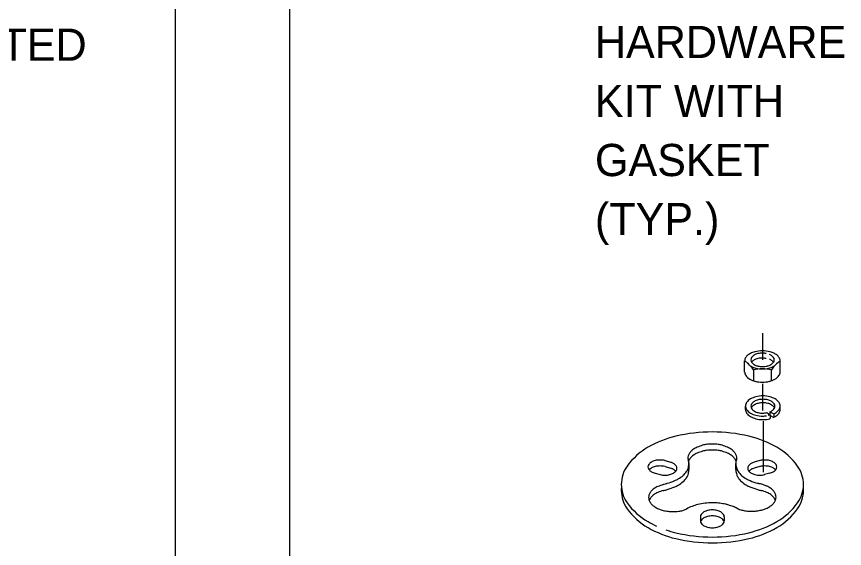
# Model space of a CAD drawing. Extents: x -224.9 to -217.6, y 224 to 234.
# Drawn here: x -219.614 to -218.072, y 230.281 to 231.272 of the extents above; entities that cross this region are included whole.
import ezdxf

# ---------------------------------------------------------------- set-up
doc = ezdxf.new("R2010")
doc.units = 0
for name, color, linetype in [('DETL-DIMS', 7, 'Continuous'), ('DETL-LINE', 7, 'Continuous'), ('DETL-NOTE', 7, 'Continuous')]:
    doc.layers.add(name, color=color, linetype=linetype)

msp = doc.modelspace()

# ---------------------------------------------------------------- linework, layer by layer
at = {"layer": 'DETL-DIMS'}
for p, q in [((-218.2241, 230.6326), (-218.2241, 230.6825)), ((-218.2241, 230.538), (-218.2241, 230.5881)), ((-218.2234, 230.4235), (-218.2234, 230.5184))]:
    msp.add_line(p, q, dxfattribs=at)
at = {"layer": 'DETL-LINE'}
for p, q in [((-219.3182, 231.7582), (-219.3182, 229.4899)), ((-219.1048, 229.4857), (-219.1048, 231.7474)), ((-218.2583, 230.6093), (-218.2583, 230.6308)), ((-218.192, 230.61), (-218.192, 230.6305)), ((-218.2419, 230.6139), (-218.2419, 230.5935)), ((-218.2086, 230.6139), (-218.2086, 230.5935)), ((-218.2569, 230.5401), (-218.2569, 230.5465)), ((-218.1919, 230.5401), (-218.1919, 230.5465)), ((-218.2172, 230.5342), (-218.2108, 230.5292)), ((-218.2108, 230.5292), (-218.2146, 230.5286)), ((-218.2111, 230.5358), (-218.2111, 230.5295)), ((-218.2111, 230.5358), (-218.2042, 230.532)), ((-218.2108, 230.5292), (-218.2108, 230.523)), ((-218.2108, 230.529), (-218.2042, 230.5254)), ((-218.2042, 230.532), (-218.2042, 230.5254)), ((-218.4065, 230.4447), (-218.396, 230.4419)), ((-218.2301, 230.4447), (-218.2407, 230.4419)), ((-218.4065, 230.4336), (-218.396, 230.4308)), ((-218.3618, 230.4283), (-218.3618, 230.4393)), ((-218.2748, 230.4283), (-218.2748, 230.4393)), ((-218.2301, 230.4336), (-218.2407, 230.4308)), ((-218.4251, 230.4213), (-218.4154, 230.4188)), ((-218.2115, 230.4213), (-218.2212, 230.4188)), ((-218.4102, 230.4001), (-218.4038, 230.4021)), ((-218.3406, 230.3401), (-218.3406, 230.3324)), ((-218.2961, 230.3401), (-218.2961, 230.3324))]:
    msp.add_line(p, q, dxfattribs=at)
for centre, radius, start, end in [((-218.2298, 230.6085), 0.0402, 103.4495, 116.0157), ((-218.2251, 230.5885), 0.0607, 90, 103.4495), ((-218.2249, 230.6076), 0.0376, 90, 103.4495), ((-218.2251, 230.5885), 0.0607, 76.5505, 90), ((-218.2263, 230.6121), 0.0331, 75.6618, 87.6727), ((-218.2203, 230.6085), 0.0402, 64.5132, 76.5505), ((-218.2207, 230.6113), 0.0378, 60, 63.3228), ((-218.2468, 230.6305), 0.0114, 144.3429, 180), ((-218.2468, 230.6305), 0.0114, 180, 180.5953), ((-218.2901, 230.5831), 0.057, 50.5728, 56.0163), ((-218.2365, 230.6231), 0.0241, 120, 144.3429), ((-218.2297, 230.6113), 0.0378, 118.0851, 120), ((-218.2392, 230.6326), 0.00754, 144.3429, 180), ((-218.2392, 230.6326), 0.00754, 180, 215.6571), ((-218.2324, 230.6278), 0.0159, 120, 144.3429), ((-218.2324, 230.6186), 0.0159, 120, 143.4298), ((-218.2279, 230.62), 0.0249, 103.4495, 120), ((-218.2279, 230.6108), 0.0249, 103.4495, 120), ((-218.2249, 230.5984), 0.0376, 90, 103.4495), ((-218.2263, 230.6029), 0.0331, 75.6618, 87.6727), ((-218.2216, 230.6162), 0.0281, 64.467, 70.2289), ((-218.2216, 230.607), 0.0281, 64.467, 70.2289), ((-218.2175, 230.6278), 0.0159, 35.6571, 60), ((-218.2175, 230.6186), 0.0159, 36.5702, 60), ((-218.2107, 230.6326), 0.00754, 0, 35.6571), ((-218.2107, 230.6326), 0.00754, 324.3429, 360), ((-218.2139, 230.6231), 0.0241, 35.6571, 60), ((-218.1609, 230.5827), 0.057, 123.2632, 128.7067), ((-218.2036, 230.6305), 0.0114, 0, 35.6571), ((-218.2036, 230.6305), 0.0114, 359.4047, 360), ((-218.2895, 230.5827), 0.057, 37.8438, 51.2933), ((-218.2354, 230.6392), 0.0215, 218.3818, 240), ((-218.2293, 230.6497), 0.0337, 240, 256.5505), ((-218.2324, 230.6375), 0.0159, 215.6571, 240), ((-218.2743, 230.5945), 0.0378, 31.0705, 37.8438), ((-218.2253, 230.5328), 0.0828, 90, 101.5646), ((-218.2279, 230.6453), 0.0249, 240, 256.5505), ((-218.2253, 230.6665), 0.0509, 256.5505, 270), ((-218.2249, 230.6576), 0.0376, 256.5505, 270), ((-218.2253, 230.6665), 0.0509, 270, 283.4495), ((-218.2253, 230.5328), 0.0828, 78.3837, 90), ((-218.2249, 230.6576), 0.0376, 270, 283.4495), ((-218.222, 230.6453), 0.0249, 283.4495, 300), ((-218.2213, 230.6497), 0.0337, 283.4495, 300), ((-218.2175, 230.6375), 0.0159, 300, 324.3429), ((-218.1761, 230.5945), 0.0378, 142.1562, 148.9295), ((-218.1609, 230.5827), 0.057, 128.7067, 142.1562), ((-218.2152, 230.6392), 0.0215, 300, 319.7392), ((-218.2468, 230.61), 0.0114, 181.3029, 215.6571), ((-218.2365, 230.6174), 0.0241, 215.6571, 240), ((-218.2139, 230.6174), 0.0241, 300, 324.3429), ((-218.2036, 230.61), 0.0114, 324.3429, 359.5811), ((-218.2297, 230.6292), 0.0378, 240, 256.5505), ((-218.2252, 230.648), 0.057, 256.5505, 270), ((-218.2252, 230.648), 0.057, 270, 283.4495), ((-218.2207, 230.6292), 0.0378, 283.4495, 300), ((-218.2456, 230.5465), 0.0112, 144.3429, 180), ((-218.2355, 230.5393), 0.0237, 120, 144.3429), ((-218.2288, 230.5276), 0.0371, 103.4495, 120), ((-218.2319, 230.5411), 0.0163, 120, 144.3429), ((-218.2273, 230.5331), 0.0256, 103.4495, 120), ((-218.2287, 230.5966), 0.0349, 251.0308, 251.1847), ((-218.2244, 230.5092), 0.0561, 90, 103.4495), ((-218.2242, 230.5204), 0.0386, 90, 103.4495), ((-218.2242, 230.5139), 0.0386, 90, 103.4495), ((-218.2244, 230.5092), 0.0561, 76.5505, 90), ((-218.2242, 230.5204), 0.0386, 76.5505, 90), ((-218.2242, 230.5139), 0.0386, 76.5505, 90), ((-218.2212, 230.5331), 0.0256, 60, 76.5505), ((-218.22, 230.5276), 0.0371, 60, 76.5505), ((-218.2204, 230.5966), 0.0349, 288.7445, 288.9692), ((-218.2166, 230.5411), 0.0163, 35.6571, 60), ((-218.2133, 230.5393), 0.0237, 35.6571, 60), ((-218.2031, 230.5465), 0.0112, 0, 35.6571), ((-218.2456, 230.5465), 0.0112, 180, 215.6571), ((-218.2456, 230.5401), 0.0112, 178.0522, 180), ((-218.2456, 230.5401), 0.0112, 180, 215.6571), ((-218.2355, 230.5538), 0.0237, 215.6571, 240), ((-218.2389, 230.5461), 0.00774, 144.3429, 180), ((-218.2389, 230.5461), 0.00774, 180, 215.6571), ((-218.2389, 230.5396), 0.00774, 144.3429, 155.3574), ((-218.2319, 230.5346), 0.0163, 120, 144.3429), ((-218.2319, 230.5511), 0.0163, 215.6571, 240), ((-218.2273, 230.5266), 0.0256, 103.4495, 120), ((-218.2212, 230.5266), 0.0256, 60, 76.5505), ((-218.2166, 230.5346), 0.0163, 35.6571, 60), ((-218.2166, 230.5511), 0.0163, 300, 324.3429), ((-218.2096, 230.5461), 0.00774, 0, 35.6571), ((-218.2096, 230.5461), 0.00774, 324.3429, 360), ((-218.2096, 230.5396), 0.00774, 24.6426, 35.6571), ((-218.2133, 230.5538), 0.0237, 300, 324.3429), ((-218.2031, 230.5465), 0.0112, 324.3429, 360), ((-218.2031, 230.5401), 0.0112, 324.3429, 360), ((-218.2031, 230.5401), 0.0112, 0, 1.3736), ((-218.2355, 230.5473), 0.0237, 215.6571, 240), ((-218.2288, 230.5654), 0.0371, 240, 256.5505), ((-218.2288, 230.559), 0.0371, 240, 256.5505), ((-218.2273, 230.5591), 0.0256, 240, 256.5505), ((-218.2244, 230.5839), 0.0561, 256.5505, 270), ((-218.2244, 230.5774), 0.0561, 256.5505, 270), ((-218.2242, 230.5718), 0.0386, 256.5505, 270), ((-218.2258, 230.5792), 0.0514, 271.5685, 279.4574), ((-218.2244, 230.5774), 0.0561, 270, 283.4495), ((-218.2256, 230.5672), 0.034, 272.3273, 284.3382), ((-218.22, 230.559), 0.0371, 283.4495, 284.3417), ((-218.2209, 230.563), 0.0289, 289.7711, 295.533), ((-218.2196, 230.5693), 0.0404, 292.5661, 296.8707), ((-218.22, 230.559), 0.0371, 295.2053, 300), ((-218.2133, 230.5473), 0.0237, 300, 324.3429), ((-218.3183, 230.2055), 0.2927, 90, 103.4495), ((-218.3183, 230.2055), 0.2927, 76.5505, 90), ((-218.3413, 230.3018), 0.1937, 103.4495, 120), ((-218.3204, 230.4007), 0.0748, 88.4495, 96.7247), ((-218.3163, 230.4007), 0.0748, 83.2753, 91.5505), ((-218.2953, 230.3018), 0.1937, 60, 76.5505), ((-218.3764, 230.3624), 0.1237, 120, 144.3429), ((-218.3384, 230.4433), 0.027, 132.1714, 146.1064), ((-218.3328, 230.4372), 0.0354, 120, 132.1714), ((-218.3357, 230.4422), 0.0296, 111.7247, 120), ((-218.278, 230.2974), 0.1855, 108.4215, 111.7247), ((-218.278, 230.2863), 0.1855, 108.4215, 111.7247), ((-218.3247, 230.4378), 0.0375, 96.7247, 108.4215), ((-218.3247, 230.4267), 0.0375, 96.7247, 108.4215), ((-218.3204, 230.3896), 0.0748, 88.4495, 96.7247), ((-218.3163, 230.3896), 0.0748, 83.2753, 91.5505), ((-218.3119, 230.4378), 0.0375, 71.5785, 83.2753), ((-218.3119, 230.4267), 0.0375, 71.5785, 83.2753), ((-218.3587, 230.2974), 0.1855, 68.2753, 71.5785), ((-218.3587, 230.2863), 0.1855, 68.2753, 71.5785), ((-218.301, 230.4422), 0.0296, 60, 68.2753), ((-218.3039, 230.4372), 0.0354, 47.8286, 60), ((-218.2983, 230.4433), 0.027, 33.8936, 47.8286), ((-218.2603, 230.3624), 0.1237, 35.6571, 60), ((-218.4191, 230.4201), 0.0254, 103.4495, 120), ((-218.416, 230.4075), 0.0384, 90, 103.4495), ((-218.416, 230.4075), 0.0384, 76.5505, 90), ((-218.413, 230.4201), 0.0254, 75.1944, 76.5505), ((-218.3525, 230.45), 0.0113, 162.1714, 183.5527), ((-218.3444, 230.4505), 0.0194, 183.5527, 194.084), ((-218.3883, 230.4364), 0.027, 17.4025, 23.3165), ((-218.3443, 230.4473), 0.0199, 146.1064, 162.1714), ((-218.3883, 230.4357), 0.027, 17.6287, 21.814), ((-218.3443, 230.4363), 0.0199, 146.1064, 156.9278), ((-218.3384, 230.4323), 0.027, 132.1714, 146.1064), ((-218.3328, 230.4261), 0.0354, 120, 132.1714), ((-218.3357, 230.4311), 0.0296, 111.7247, 120), ((-218.301, 230.4311), 0.0296, 60, 68.2753), ((-218.3039, 230.4261), 0.0354, 47.8286, 60), ((-218.2983, 230.4323), 0.027, 33.8936, 47.8286), ((-218.2924, 230.4473), 0.0199, 17.8286, 33.8936), ((-218.2924, 230.4363), 0.0199, 23.0722, 33.8936), ((-218.2483, 230.4364), 0.027, 156.6835, 162.5975), ((-218.2483, 230.4364), 0.027, 156.6835, 162.5975), ((-218.2842, 230.45), 0.0113, 356.4472, 17.8286), ((-218.2923, 230.4505), 0.0194, 349.9031, 356.4472), ((-218.2236, 230.4201), 0.0254, 103.4495, 104.8056), ((-218.2206, 230.4075), 0.0384, 90, 103.4495), ((-218.2206, 230.4075), 0.0384, 76.5505, 90), ((-218.2176, 230.4201), 0.0254, 60, 76.5505), ((-218.4292, 230.4003), 0.0587, 144.3429, 180), ((-218.4306, 230.4331), 0.0077, 144.3429, 180), ((-218.4306, 230.4331), 0.0077, 180, 215.6571), ((-218.4236, 230.4281), 0.0162, 120, 144.3429), ((-218.4236, 230.417), 0.0162, 120, 139.6335), ((-218.4191, 230.4091), 0.0254, 103.4495, 120), ((-218.416, 230.3964), 0.0384, 90, 103.4495), ((-218.416, 230.3964), 0.0384, 76.5505, 90), ((-218.413, 230.4091), 0.0254, 75.1944, 76.5505), ((-218.4035, 230.4176), 0.0254, 60, 72.7643), ((-218.4035, 230.4065), 0.0254, 60, 72.7643), ((-218.3989, 230.4256), 0.0162, 35.6571, 60), ((-218.392, 230.4305), 0.0077, 0, 35.6571), ((-218.392, 230.4305), 0.0077, 324.3429, 360), ((-218.3847, 230.437), 0.0221, 326.1862, 342.1714), ((-218.4024, 230.4427), 0.0407, 342.1714, 353.9334), ((-218.3769, 230.4393), 0.015, 0.0001, 17.6287), ((-218.3768, 230.44), 0.015, 353.9334, 17.4025), ((-218.2599, 230.44), 0.015, 162.5975, 186.0666), ((-218.2599, 230.44), 0.015, 162.5975, 186.0666), ((-218.2343, 230.4427), 0.0407, 186.0666, 197.8286), ((-218.2343, 230.4427), 0.0407, 186.0666, 197.8286), ((-218.252, 230.437), 0.0221, 197.8286, 213.8138), ((-218.252, 230.437), 0.0221, 197.8286, 213.8138), ((-218.2447, 230.4305), 0.0077, 144.3429, 180), ((-218.2447, 230.4305), 0.0077, 180, 215.6571), ((-218.2378, 230.4256), 0.0162, 120, 144.3429), ((-218.2332, 230.4176), 0.0254, 107.2357, 120), ((-218.2332, 230.4065), 0.0254, 107.2357, 120), ((-218.2236, 230.4091), 0.0254, 103.4495, 104.8056), ((-218.2206, 230.3964), 0.0384, 90, 103.4495), ((-218.2206, 230.3964), 0.0384, 76.5505, 90), ((-218.2176, 230.4091), 0.0254, 60, 76.5505), ((-218.213, 230.4281), 0.0162, 35.6571, 60), ((-218.213, 230.417), 0.0162, 40.3665, 60), ((-218.2061, 230.4331), 0.0077, 360, 35.6571), ((-218.2061, 230.4331), 0.0077, 324.3429, 360), ((-218.2074, 230.4003), 0.0587, 0, 35.6571), ((-218.4236, 230.438), 0.0162, 215.6571, 240), ((-218.4191, 230.446), 0.0254, 240, 256.1867), ((-218.4095, 230.4435), 0.0254, 255.8168, 256.5505), ((-218.4065, 230.4561), 0.0384, 256.5505, 270), ((-218.4065, 230.4561), 0.0384, 270, 283.4495), ((-218.4035, 230.4435), 0.0254, 283.4495, 300), ((-218.3989, 230.4145), 0.0162, 40.3665, 60), ((-218.3989, 230.4355), 0.0162, 300, 324.3429), ((-218.4083, 230.4566), 0.053, 300, 312.1714), ((-218.3996, 230.447), 0.04, 312.1714, 326.1862), ((-218.3846, 230.4252), 0.022, 326.1437, 342.1714), ((-218.4025, 230.431), 0.0408, 342.1714, 353.9054), ((-218.3769, 230.4283), 0.015, 353.9054, 0.0001), ((-218.2598, 230.4283), 0.015, 179.9999, 186.0946), ((-218.2341, 230.431), 0.0408, 186.0946, 197.8286), ((-218.2521, 230.4252), 0.022, 197.8286, 213.8563), ((-218.2371, 230.447), 0.04, 213.8138, 227.8286), ((-218.2371, 230.447), 0.04, 213.8138, 227.8286), ((-218.2284, 230.4566), 0.053, 227.8286, 240), ((-218.2284, 230.4566), 0.053, 227.8286, 240), ((-218.2378, 230.4355), 0.0162, 215.6571, 240), ((-218.2378, 230.4145), 0.0162, 120, 139.6335), ((-218.2332, 230.4435), 0.0254, 240, 256.5505), ((-218.2301, 230.4561), 0.0384, 256.5505, 270), ((-218.2301, 230.4561), 0.0384, 270, 283.4495), ((-218.2271, 230.4435), 0.0254, 283.4495, 284.1832), ((-218.2176, 230.446), 0.0254, 283.8133, 300), ((-218.213, 230.438), 0.0162, 300, 324.3429), ((-218.4292, 230.4003), 0.0587, 180, 215.6571), ((-218.3579, 230.2416), 0.1668, 108.2479, 111.7247), ((-218.4149, 230.4414), 0.0408, 285.762, 287.601), ((-218.4651, 230.5999), 0.2071, 287.601, 291.7247), ((-218.4075, 230.4553), 0.0515, 291.7247, 300), ((-218.4069, 230.4426), 0.0503, 291.7247, 300), ((-218.4083, 230.4448), 0.0529, 300, 312.1714), ((-218.3997, 230.4354), 0.0402, 312.1714, 326.1437), ((-218.2369, 230.4354), 0.0402, 213.8563, 227.8286), ((-218.2284, 230.4448), 0.0529, 227.8286, 240), ((-218.2291, 230.4553), 0.0515, 240, 248.2753), ((-218.2291, 230.4553), 0.0515, 240, 248.2753), ((-218.2297, 230.4426), 0.0503, 240, 248.2753), ((-218.1715, 230.5999), 0.2071, 248.2753, 252.399), ((-218.1715, 230.5999), 0.2071, 248.2753, 252.399), ((-218.2218, 230.4414), 0.0408, 252.399, 254.238), ((-218.2218, 230.4414), 0.0408, 252.399, 254.238), ((-218.2433, 230.3282), 0.0746, 80.3565, 81.9421), ((-218.2356, 230.3739), 0.0283, 72.3032, 80.3565), ((-218.2705, 230.2644), 0.1432, 68.2753, 72.3032), ((-218.2074, 230.4003), 0.0587, 324.3429, 360), ((-218.4292, 230.3893), 0.0587, 174.5836, 180), ((-218.4292, 230.3893), 0.0587, 180, 215.6571), ((-218.4189, 230.3751), 0.0183, 146.1064, 162.1714), ((-218.4117, 230.3702), 0.027, 132.1714, 146.1064), ((-218.4061, 230.364), 0.0354, 120, 132.1714), ((-218.4061, 230.3529), 0.0354, 120, 132.1714), ((-218.4081, 230.3675), 0.0314, 111.7247, 120), ((-218.4081, 230.3564), 0.0314, 111.7247, 120), ((-218.3579, 230.2306), 0.1668, 108.2479, 111.7247), ((-218.4269, 230.4991), 0.1114, 278.6437, 279.517), ((-218.4156, 230.4316), 0.043, 279.517, 287.7431), ((-218.4686, 230.5974), 0.217, 287.7431, 291.7247), ((-218.168, 230.5974), 0.217, 248.2753, 252.2569), ((-218.221, 230.4316), 0.043, 252.2569, 260.483), ((-218.2097, 230.4991), 0.1114, 260.483, 261.3563), ((-218.2787, 230.2306), 0.1668, 68.2753, 71.7521), ((-218.2301, 230.3659), 0.034, 60, 68.2753), ((-218.2286, 230.3564), 0.0314, 60, 68.2753), ((-218.2308, 230.3646), 0.0354, 47.8286, 60), ((-218.2306, 230.3529), 0.0354, 47.8286, 60), ((-218.2252, 230.3708), 0.027, 33.8936, 47.8286), ((-218.2179, 230.3757), 0.0183, 17.8286, 33.8936), ((-218.2074, 230.3893), 0.0587, 324.3429, 360), ((-218.2074, 230.3893), 0.0587, 0, 5.4164), ((-218.4222, 230.3761), 0.0149, 162.1714, 180), ((-218.4222, 230.3761), 0.0149, 180, 197.8286), ((-218.4189, 230.3772), 0.0183, 197.8286, 213.8936), ((-218.4189, 230.364), 0.0183, 146.1064, 158.9259), ((-218.4117, 230.3591), 0.027, 132.1714, 146.1064), ((-218.2252, 230.3827), 0.027, 312.1714, 326.1064), ((-218.225, 230.3591), 0.027, 33.8936, 47.8286), ((-218.2179, 230.3778), 0.0183, 326.1064, 342.1714), ((-218.2177, 230.364), 0.0183, 21.0741, 33.8936), ((-218.2147, 230.3767), 0.0149, 360, 17.8286), ((-218.2147, 230.3767), 0.0149, 342.1714, 0), ((-218.3764, 230.4382), 0.1237, 215.6571, 240), ((-218.3764, 230.4272), 0.1237, 215.6571, 240), ((-218.4117, 230.382), 0.027, 213.8936, 227.8286), ((-218.4061, 230.3882), 0.0354, 227.8286, 240), ((-218.3978, 230.4025), 0.0519, 240, 248.2753), ((-218.3977, 230.4027), 0.0521, 248.2753, 256.5288), ((-218.3962, 230.4328), 0.0839, 285.7752, 290.1641), ((-218.3415, 230.3117), 0.0495, 120, 121.9864), ((-218.3275, 230.2875), 0.0775, 103.4495, 120), ((-218.3183, 230.249), 0.1171, 90, 103.4495), ((-218.3183, 230.3145), 0.0384, 90, 103.4495), ((-218.3151, 230.2438), 0.1223, 87.3973, 91.5193), ((-218.3183, 230.3145), 0.0384, 76.5505, 90), ((-218.3113, 230.3271), 0.0389, 80.0864, 87.3973), ((-218.4236, 229.6846), 0.6912, 79.1532, 80.0864), ((-218.2999, 230.3302), 0.0338, 74.9328, 79.1532), ((-218.3067, 230.3047), 0.0602, 71.8003, 74.9328), ((-218.4286, 229.934), 0.4504, 70.6551, 71.8003), ((-218.2916, 230.3244), 0.0367, 64.9628, 70.6551), ((-218.2965, 230.314), 0.0482, 60, 64.9628), ((-218.2554, 230.3962), 0.0438, 247.3083, 248.2753), ((-218.2413, 230.4315), 0.0819, 248.2753, 254.3263), ((-218.2498, 230.4014), 0.0506, 254.3263, 263.2753), ((-218.2452, 230.4286), 0.0781, 276.7247, 283.4712), ((-218.2391, 230.4034), 0.0521, 283.4712, 291.7247), ((-218.239, 230.4031), 0.0519, 291.7247, 300), ((-218.2308, 230.3889), 0.0354, 300, 312.1714), ((-218.2603, 230.4382), 0.1237, 300, 324.3429), ((-218.2603, 230.4272), 0.1237, 300, 324.3429), ((-218.3917, 230.4279), 0.0781, 256.5288, 263.2753), ((-218.3916, 230.4284), 0.0786, 263.2753, 270), ((-218.3916, 230.4399), 0.09, 270, 276.7247), ((-218.3869, 230.3999), 0.0498, 276.7247, 285.7752), ((-218.3329, 230.3401), 0.0077, 144.3429, 180), ((-218.3259, 230.3351), 0.0162, 120, 144.3429), ((-218.3259, 230.324), 0.0162, 120, 144.3429), ((-218.3213, 230.3271), 0.0254, 103.4495, 120), ((-218.3213, 230.316), 0.0254, 103.4495, 120), ((-218.3183, 230.3034), 0.0384, 90, 103.4495), ((-218.3183, 230.3034), 0.0384, 76.5505, 90), ((-218.3153, 230.3271), 0.0254, 60, 76.5505), ((-218.3153, 230.316), 0.0254, 60, 76.5505), ((-218.3107, 230.3351), 0.0162, 35.6571, 60), ((-218.3107, 230.324), 0.0162, 35.6571, 60), ((-218.3038, 230.3401), 0.0077, 0, 35.6571), ((-218.2452, 230.4401), 0.0896, 263.2753, 270), ((-218.2452, 230.4291), 0.0786, 270, 276.7247), ((-218.3413, 230.4989), 0.1937, 240, 245.3427), ((-218.3329, 230.3324), 0.0077, 180, 215.6571), ((-218.3329, 230.329), 0.0077, 144.3429, 167.1006), ((-218.3259, 230.3374), 0.0162, 215.6571, 240), ((-218.3213, 230.3453), 0.0254, 240, 256.5505), ((-218.3153, 230.3453), 0.0254, 283.4495, 300), ((-218.3107, 230.3374), 0.0162, 300, 324.3429), ((-218.3038, 230.329), 0.0077, 12.8994, 35.6571), ((-218.3038, 230.3324), 0.0077, 324.3429, 0), ((-218.2953, 230.4989), 0.1937, 283.4495, 300), ((-218.3413, 230.4878), 0.1937, 240, 256.5505), ((-218.3413, 230.4989), 0.1937, 250.8196, 256.5505), ((-218.3183, 230.5951), 0.2927, 256.5505, 270), ((-218.3183, 230.358), 0.0384, 256.5505, 270), ((-218.3183, 230.358), 0.0384, 270, 283.4495), ((-218.3183, 230.5951), 0.2927, 270, 283.4495), ((-218.2953, 230.4878), 0.1937, 283.4495, 300), ((-218.3183, 230.5841), 0.2927, 256.5505, 270), ((-218.3183, 230.5841), 0.2927, 270, 283.4495)]:
    msp.add_arc(centre, radius, start, end, dxfattribs=at)

# ---------------------------------------------------------------- texts
at = {"layer": 'DETL-NOTE'}
for s, p in [('SERRATED', (-219.9201, 231.1898)), ('HARDWARE', (-218.537, 231.1949)), ('KIT WITH', (-218.537, 231.0849)), ('GASKET', (-218.537, 230.9749)), ('(TYP.)', (-218.537, 230.8649))]:
    msp.add_text(s, height=0.06, dxfattribs=at).set_placement(p)

doc.saveas('drawing.dxf')
